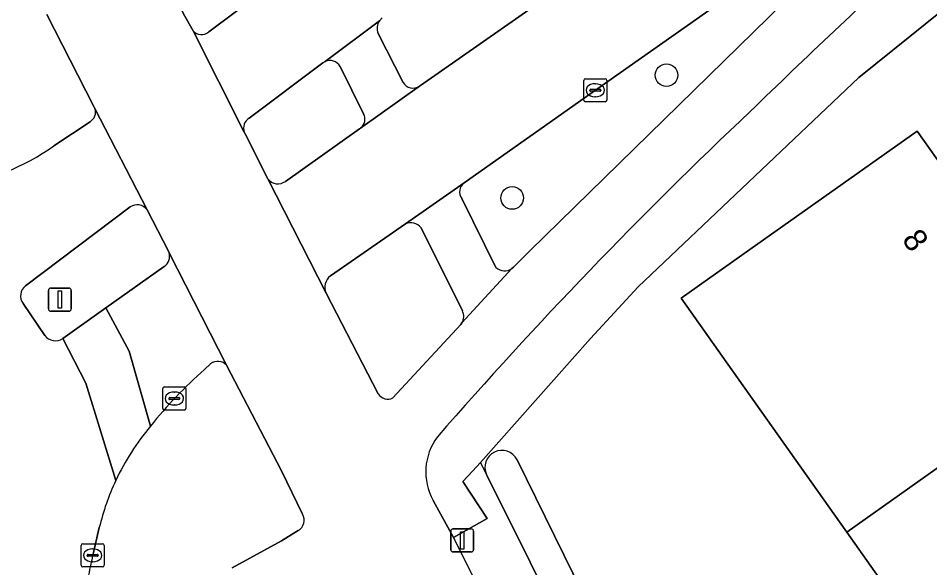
# Model space of a CAD drawing. Extents: x 158455 to 159797, y 387218 to 388672.
# Drawn here: x 159177.48 to 159216.88, y 387740.08 to 387763.85 of the extents above; entities that cross this region are included whole.
import ezdxf

# ---------------------------------------------------------------- set-up
doc = ezdxf.new("R2010")
doc.units = 0
for name, color, linetype in [('IMGEO_Berm_groen', 7, 'Continuous'), ('IMGEO_Boom', 7, 'Continuous'), ('IMGEO_Erf', 7, 'Continuous'), ('IMGEO_Fietspad_open', 7, 'Continuous'), ('IMGEO_Kolk', 7, 'Continuous'), ('IMGEO_Lichtmast', 7, 'Continuous'), ('IMGEO_Pand', 7, 'Continuous'), ('IMGEO_Pand_nummerreeks', 7, 'Continuous'), ('IMGEO_Rijbaan_lokaal_gesloten', 7, 'Continuous'), ('IMGEO_Verkeerseiland_groen', 7, 'Continuous'), ('IMGEO_Voetpad_open', 7, 'Continuous'), ('IMGEO_Waterloop', 7, 'Continuous')]:
    doc.layers.add(name, color=color, linetype=linetype)

msp = doc.modelspace()

# ---------------------------------------------------------------- linework, layer by layer
at = {"layer": 'IMGEO_Berm_groen'}
for points in [[(159194.829, 387760.914), (159194.871, 387760.944), (159201.836, 387765.824)], [(159180.793, 387759.947), (159180.737, 387760.058), (159178.711, 387764.013)], [(159193.037, 387763.192), (159194.114, 387761.073)], [(159179.013, 387758.326), (159180.582, 387759.371)], [(159197.72, 387744.115), (159197.458, 387744.641), (159197.12, 387744.26), (159196.694, 387743.819), (159197.747, 387742.215), (159196.287, 387741.387), (159199.422, 387735.133), (159203.135, 387727.729), (159203.744, 387726.53), (159209.072, 387716.044), (159215.088, 387713.348), (159215.858, 387713.235), (159217.158, 387713.181), (159235.947, 387712.585), (159235.969, 387713.133), (159236.15, 387717.664), (159235.73, 387717.691), (159234.304, 387717.222)], [(159210.934, 387717.576), (159197.72, 387744.115)]]:
    msp.add_lwpolyline(points, dxfattribs=at)
for centre, radius, start, end in [((159193.535, 387763.415), 0.546, 143.5726, 204.115), ((159193.553, 387763.402), 0.568, 127.9426, 143.6271), ((159194.549, 387761.342), 0.512, 211.7615, 303.1639), ((159180.336, 387759.788), 0.484, 300.5909, 19.1716), ((159173.217, 387766.521), 10.038, 278.3038, 305.2672)]:
    msp.add_arc(centre, radius, start, end, dxfattribs=at)
at = {"layer": 'IMGEO_Boom'}
for centre in [(159205.5, 387761.384), (159198.83, 387756.077)]:
    msp.add_circle(centre, 0.489, dxfattribs=at)
at = {"layer": 'IMGEO_Erf'}
for points in [[(159236.179, 387728.753), (159235.227, 387730.066), (159229.26, 387738.298), (159232.294, 387740.557), (159225.442, 387750), (159223.511, 387752.661), (159224.515, 387753.447), (159223.591, 387757.291), (159218.155, 387764.796), (159213.819, 387761.288), (159204.282, 387752.237), (159202.211, 387750), (159197.458, 387744.641), (159197.72, 387744.115)], [(159217.899, 387735.111), (159213.29, 387741.626), (159208.321, 387748.651), (159206.13, 387751.748), (159209.096, 387753.846), (159216.34, 387758.971), (159220.621, 387752.92)], [(159199.04, 387744.753), (159211.918, 387718.548)]]:
    msp.add_lwpolyline(points, dxfattribs=at)
msp.add_arc((159198.382, 387744.429), 0.733, 26.2174, 205.3746, dxfattribs=at)
at = {"layer": 'IMGEO_Fietspad_open'}
for points in [[(159216.449, 387766.728), (159214.491, 387768.328), (159213.131, 387767.053), (159199.59, 387753.792), (159198.894, 387753.089), (159198.822, 387753.027), (159196.659, 387750.67), (159196.609, 387750.601), (159193.667, 387747.428)], [(159193.037, 387747.602), (159190.786, 387751.953), (159188.274, 387756.909), (159187.3, 387758.822), (159187.247, 387758.928), (159185.04, 387763.304), (159184.617, 387764.04), (159183.73, 387765.91)], [(159178.711, 387764.013), (159180.737, 387760.058), (159180.793, 387759.947), (159183.05, 387755.565), (159183.974, 387753.779), (159184.002, 387753.705), (159186.488, 387748.842), (159188.852, 387744.277), (159189.771, 387742.404)], [(159188.426, 387738.045), (159190.99, 387739.621), (159191.191, 387739.744), (159191.822, 387738.536), (159194.686, 387732.684), (159199.422, 387735.133), (159196.287, 387741.387), (159195.41, 387742.999)], [(159189.581, 387741.691), (159188.857, 387741.243), (159186.728, 387740.084)]]:
    msp.add_lwpolyline(points, dxfattribs=at)
for centre, radius, start, end in [((159441.931, 387520.228), 334.072, 132.45033, 134.17723), ((159347.221, 387613.579), 201.141, 133.35949, 138.92324), ((159193.45, 387747.87), 0.492, 212.9441, 296.1766), ((159197.638, 387744.227), 2.544, 143.4188, 208.8672), ((159189.302, 387742.147), 0.534, 301.4159, 28.7413)]:
    msp.add_arc(centre, radius, start, end, dxfattribs=at)
at = {"layer": 'IMGEO_Kolk'}
for p, q in [((159201.924, 387760.309), (159201.924, 387761.161)), ((159201.999, 387761.235), (159202.851, 387761.235)), ((159202.925, 387761.161), (159202.925, 387760.309)), ((159202.183, 387760.729), (159202.183, 387760.741)), ((159202.226, 387760.778), (159202.624, 387760.778)), ((159202.412, 387761.015), (159202.437, 387761.015)), ((159202.667, 387760.741), (159202.667, 387760.729)), ((159202.621, 387760.692), (159202.223, 387760.692)), ((159202.435, 387760.455), (159202.41, 387760.455)), ((159202.851, 387760.235), (159201.999, 387760.235)), ((159183.727, 387746.978), (159183.727, 387747.83)), ((159183.802, 387747.904), (159184.654, 387747.904)), ((159184.728, 387747.83), (159184.728, 387746.978)), ((159183.986, 387747.398), (159183.986, 387747.41)), ((159184.424, 387747.361), (159184.026, 387747.361)), ((159184.029, 387747.447), (159184.427, 387747.447)), ((159184.215, 387747.684), (159184.24, 387747.684)), ((159184.47, 387747.41), (159184.47, 387747.398)), ((159184.238, 387747.124), (159184.213, 387747.124)), ((159184.654, 387746.904), (159183.802, 387746.904)), ((159180.196, 387740.196), (159180.196, 387741.048)), ((159180.271, 387741.122), (159181.123, 387741.122)), ((159181.197, 387741.048), (159181.197, 387740.196)), ((159180.455, 387740.616), (159180.455, 387740.628)), ((159180.498, 387740.665), (159180.896, 387740.665)), ((159180.684, 387740.902), (159180.709, 387740.902)), ((159180.939, 387740.628), (159180.939, 387740.616)), ((159180.893, 387740.579), (159180.495, 387740.579)), ((159180.707, 387740.342), (159180.682, 387740.342)), ((159181.123, 387740.122), (159180.271, 387740.122))]:
    msp.add_line(p, q, dxfattribs=at)
for points in [[(159201.924, 387760.309), (159201.924, 387761.161)], [(159201.999, 387761.235), (159202.851, 387761.235)], [(159202.925, 387761.161), (159202.925, 387760.309)], [(159202.851, 387760.235), (159201.999, 387760.235)], [(159183.727, 387746.978), (159183.727, 387747.83)], [(159183.802, 387747.904), (159184.654, 387747.904)], [(159184.728, 387747.83), (159184.728, 387746.978)], [(159184.654, 387746.904), (159183.802, 387746.904)], [(159180.196, 387740.196), (159180.196, 387741.048)], [(159180.271, 387741.122), (159181.123, 387741.122)], [(159181.197, 387741.048), (159181.197, 387740.196)], [(159181.123, 387740.122), (159180.271, 387740.122)]]:
    msp.add_lwpolyline(points, dxfattribs=at)
for centre, radius, start, end in [((159202.001, 387761.159), 0.0765, 91.552, 178.448), ((159202.001, 387761.159), 0.0765, 91.552, 178.448), ((159202.849, 387761.159), 0.0765, 1.552, 88.448), ((159202.849, 387761.159), 0.0765, 1.552, 88.448), ((159202.223, 387760.738), 0.0403, 85.8775, 175.7526), ((159202.22, 387760.728), 0.0366, 178.938, 274.7102), ((159202.624, 387760.735), 0.043, 264.8664, 352.4533), ((159202.628, 387760.74), 0.0386, 1.7309, 96.639), ((159202.001, 387760.311), 0.0765, 181.552, 268.448), ((159202.001, 387760.311), 0.0765, 181.552, 268.448), ((159202.849, 387760.311), 0.0765, 271.552, 358.448), ((159202.849, 387760.311), 0.0765, 271.552, 358.448), ((159183.804, 387747.828), 0.0765, 91.552, 178.448), ((159183.804, 387747.828), 0.0765, 91.552, 178.448), ((159184.652, 387747.828), 0.0765, 1.552, 88.448), ((159184.652, 387747.828), 0.0765, 1.552, 88.448), ((159184.026, 387747.407), 0.0403, 85.8775, 175.7526), ((159184.023, 387747.397), 0.0366, 178.938, 274.7102), ((159184.427, 387747.404), 0.043, 264.8664, 352.4533), ((159184.431, 387747.409), 0.0386, 1.7309, 96.639), ((159183.804, 387746.98), 0.0765, 181.552, 268.448), ((159183.804, 387746.98), 0.0765, 181.552, 268.448), ((159184.652, 387746.98), 0.0765, 271.552, 358.448), ((159184.652, 387746.98), 0.0765, 271.552, 358.448), ((159180.273, 387741.046), 0.0765, 91.552, 178.448), ((159180.273, 387741.046), 0.0765, 91.552, 178.448), ((159181.121, 387741.046), 0.0765, 1.552, 88.448), ((159181.121, 387741.046), 0.0765, 1.552, 88.448), ((159180.495, 387740.625), 0.0403, 85.8775, 175.7526), ((159180.9, 387740.627), 0.0386, 1.7309, 96.639), ((159180.492, 387740.615), 0.0366, 178.938, 274.7102), ((159180.896, 387740.622), 0.043, 264.8664, 352.4533), ((159180.273, 387740.198), 0.0765, 181.552, 268.448), ((159180.273, 387740.198), 0.0765, 181.552, 268.448), ((159181.121, 387740.198), 0.0765, 271.552, 358.448), ((159181.121, 387740.198), 0.0765, 271.552, 358.448)]:
    msp.add_arc(centre, radius, start, end, dxfattribs=at)
for centre, major_axis, ratio, start_param, end_param in [((159202.411, 387760.735), (-0.387, 0.002), 0.722429, 4.712389, 7.853982), ((159202.436, 387760.735), (-0.39, 0.002), 0.717154, 1.570796, 4.712389), ((159184.214, 387747.404), (-0.387, 0.002), 0.722429, 4.712389, 7.853982), ((159184.239, 387747.404), (-0.39, 0.002), 0.717154, 1.570796, 4.712389), ((159180.683, 387740.622), (-0.387, 0.002), 0.722429, 4.712389, 7.853982), ((159180.708, 387740.622), (-0.39, 0.002), 0.717154, 1.570796, 4.712389)]:
    msp.add_ellipse(centre, major_axis=major_axis, ratio=ratio, start_param=start_param, end_param=end_param, dxfattribs=at)
at = {"layer": 'IMGEO_Lichtmast'}
for p, q in [((159178.784, 387751.28), (159178.784, 387752.08)), ((159178.784, 387752.08), (159178.784, 387751.28)), ((159178.884, 387752.18), (159179.674, 387752.18)), ((159179.674, 387752.18), (159178.884, 387752.18)), ((159179.774, 387752.08), (159179.774, 387751.28)), ((159179.774, 387751.28), (159179.774, 387752.08)), ((159179.674, 387751.18), (159178.884, 387751.18)), ((159178.884, 387751.18), (159179.674, 387751.18)), ((159196.172, 387740.867), (159196.172, 387741.667)), ((159196.172, 387741.667), (159196.172, 387740.867)), ((159196.272, 387741.767), (159197.062, 387741.767)), ((159197.062, 387741.767), (159196.272, 387741.767)), ((159197.162, 387741.667), (159197.162, 387740.867)), ((159197.162, 387740.867), (159197.162, 387741.667)), ((159197.062, 387740.767), (159196.272, 387740.767)), ((159196.272, 387740.767), (159197.062, 387740.767))]:
    msp.add_line(p, q, dxfattribs=at)
for points in [[(159179.204, 387752.055), (159179.354, 387752.055), (159179.354, 387751.305), (159179.204, 387751.305), (159179.204, 387752.055)], [(159196.592, 387741.642), (159196.742, 387741.642), (159196.742, 387740.892), (159196.592, 387740.892), (159196.592, 387741.642)]]:
    msp.add_lwpolyline(points, dxfattribs=at)
for centre, start, end in [((159178.884, 387752.08), 90, 180), ((159178.884, 387752.08), 90, 180), ((159179.674, 387752.08), 0, 90), ((159179.674, 387752.08), 360, 90), ((159178.884, 387751.28), 180, 270), ((159178.884, 387751.28), 180, 270), ((159179.674, 387751.28), 270, 0), ((159179.674, 387751.28), 270, 0), ((159196.272, 387741.667), 90, 180), ((159196.272, 387741.667), 90, 180), ((159197.062, 387741.667), 0, 90), ((159197.062, 387741.667), 360, 90), ((159196.272, 387740.867), 180, 270), ((159196.272, 387740.867), 180, 270), ((159197.062, 387740.867), 270, 0), ((159197.062, 387740.867), 270, 0)]:
    msp.add_arc(centre, 0.1, start, end, dxfattribs=at)
at = {"layer": 'IMGEO_Pand'}
for points in [[(159217.973, 387751.046), (159220.621, 387752.92), (159216.34, 387758.971), (159209.096, 387753.846), (159206.13, 387751.748), (159208.321, 387748.651), (159213.29, 387741.626), (159219.44, 387745.978), (159220.851, 387746.977), (159218.713, 387750)], [(159219.527, 387745.855), (159219.44, 387745.978), (159213.29, 387741.626), (159217.899, 387735.111), (159219.374, 387736.154), (159221.405, 387733.283), (159221.54, 387733.092), (159224.79, 387735.39), (159228.92, 387738.31), (159224.896, 387743.997), (159222.194, 387742.085)]]:
    msp.add_lwpolyline(points, close=True, dxfattribs=at)
at = {"layer": 'IMGEO_Rijbaan_lokaal_gesloten'}
for points in [[(159206.931, 387769.424), (159204.04, 387767.381), (159201.836, 387765.824), (159194.871, 387760.944), (159194.829, 387760.914), (159192.279, 387759.096), (159192.256, 387759.079), (159192.233, 387759.064), (159189.028, 387756.796)], [(159190.974, 387752.703), (159194.223, 387754.955), (159196.748, 387756.729), (159202.425, 387760.735), (159214.068, 387768.944)], [(159194.975, 387765.188), (159192.602, 387768.409), (159191.435, 387767.536), (159189.023, 387765.739), (159185.711, 387763.256)], [(159187.459, 387759.529), (159190.644, 387761.924), (159190.744, 387761.979), (159193.096, 387763.739)], [(159185.04, 387763.304), (159187.247, 387758.928)], [(159183.05, 387755.565), (159180.793, 387759.947)], [(159180.582, 387759.371), (159179.013, 387758.326)], [(159188.274, 387756.909), (159190.786, 387751.953)], [(159177.796, 387752.278), (159182.318, 387755.692)], [(159186.488, 387748.842), (159184.002, 387753.705)], [(159183.792, 387753.111), (159181.266, 387751.323), (159182.275, 387749.457), (159183.195, 387746.204)], [(159178.63, 387750.132), (159177.689, 387751.508)], [(159182.275, 387749.457), (159181.266, 387751.323), (159179.4, 387750.002), (159180.407, 387748.068), (159181.694, 387743.855)], [(159181.694, 387743.855), (159180.407, 387748.068), (159179.4, 387750.002)], [(159183.195, 387746.204), (159182.275, 387749.457)], [(159185.533, 387748.652), (159185.796, 387748.908)], [(159180.697, 387740.622), (159180.984, 387741.83)]]:
    msp.add_lwpolyline(points, dxfattribs=at)
for centre, radius, start, end in [((159193.553, 387763.402), 0.568, 127.9426, 143.6271), ((159185.399, 387763.609), 0.471, 220.331, 311.4856), ((159180.336, 387759.788), 0.484, 300.5909, 19.1716), ((159187.718, 387759.1), 0.501, 121.0889, 200.0509), ((159173.217, 387766.521), 10.038, 278.3038, 305.2672), ((159188.705, 387757.216), 0.53, 215.4314, 307.5219), ((159182.617, 387755.239), 0.542, 36.9041, 123.4105), ((159183.486, 387753.553), 0.538, 304.676, 16.3834), ((159191.359, 387752.208), 0.627, 127.8536, 204.002), ((159178.139, 387751.838), 0.558, 127.9599, 216.2177), ((159179.082, 387750.463), 0.56, 216.2482, 304.5859), ((159186.105, 387748.484), 0.524, 43.0251, 126.0786), ((159197.563, 387734.823), 18.329, 131.0183, 141.615), ((159191.477, 387739.258), 10.809, 140.0131, 154.8301), ((159191.214, 387739.38), 10.519, 154.8242, 166.5327), ((159196.205, 387737.027), 15.92, 166.9478, 170.5665)]:
    msp.add_arc(centre, radius, start, end, dxfattribs=at)
at = {"layer": 'IMGEO_Verkeerseiland_groen'}
for points in [[(159214.068, 387768.944), (159202.425, 387760.735), (159196.748, 387756.729)], [(159198.822, 387753.027), (159198.894, 387753.089), (159199.59, 387753.792), (159213.131, 387767.053)], [(159183.73, 387765.91), (159184.617, 387764.04), (159185.04, 387763.304)], [(159185.711, 387763.256), (159189.023, 387765.739)], [(159190.744, 387761.979), (159190.644, 387761.924), (159187.459, 387759.529)], [(159192.404, 387759.722), (159191.396, 387761.766)], [(159187.247, 387758.928), (159187.3, 387758.822), (159188.274, 387756.909)], [(159189.028, 387756.796), (159192.233, 387759.064), (159192.256, 387759.079), (159192.279, 387759.096)], [(159196.648, 387756.059), (159198.13, 387753.067)], [(159182.318, 387755.692), (159177.796, 387752.278)], [(159184.002, 387753.705), (159183.974, 387753.779), (159183.05, 387755.565)], [(159194.223, 387754.955), (159190.974, 387752.703)], [(159196.676, 387751.195), (159194.891, 387754.786)], [(159179.4, 387750.002), (159181.266, 387751.323), (159183.792, 387753.111)], [(159190.786, 387751.953), (159193.037, 387747.602)], [(159177.689, 387751.508), (159178.63, 387750.132)], [(159193.667, 387747.428), (159196.609, 387750.601), (159196.659, 387750.67)], [(159185.796, 387748.908), (159185.533, 387748.652)], [(159189.771, 387742.404), (159188.852, 387744.277), (159186.488, 387748.842)], [(159180.984, 387741.83), (159180.697, 387740.622)], [(159186.728, 387740.084), (159188.857, 387741.243), (159189.581, 387741.691)]]:
    msp.add_lwpolyline(points, dxfattribs=at)
for centre, radius, start, end in [((159185.399, 387763.609), 0.471, 220.331, 311.4856), ((159190.947, 387761.496), 0.524, 31.0493, 112.7676), ((159191.976, 387759.482), 0.491, 308.1676, 29.2477), ((159187.718, 387759.1), 0.501, 121.0889, 200.0509), ((159188.705, 387757.216), 0.53, 215.4314, 307.5219), ((159197.045, 387756.342), 0.488, 127.5359, 215.4862), ((159182.617, 387755.239), 0.542, 36.9041, 123.4105), ((159194.443, 387754.421), 0.577, 39.1744, 112.4304), ((159183.486, 387753.553), 0.538, 304.676, 16.3834), ((159198.501, 387753.474), 0.55, 227.6501, 305.7335), ((159191.359, 387752.208), 0.627, 127.8536, 204.002), ((159178.139, 387751.838), 0.558, 127.9599, 216.2177), ((159196.204, 387750.948), 0.533, 328.628, 27.6627), ((159179.082, 387750.463), 0.56, 216.2482, 304.5859), ((159186.105, 387748.484), 0.524, 43.0251, 126.0786), ((159197.563, 387734.823), 18.329, 131.0183, 141.615), ((159193.45, 387747.87), 0.492, 212.9441, 296.1766), ((159191.477, 387739.258), 10.809, 140.0131, 154.8301), ((159191.214, 387739.38), 10.519, 154.8242, 166.5327), ((159189.302, 387742.147), 0.534, 301.4159, 28.7413), ((159196.205, 387737.027), 15.92, 166.9478, 170.5665)]:
    msp.add_arc(centre, radius, start, end, dxfattribs=at)
at = {"layer": 'IMGEO_Voetpad_open'}
for points in [[(159195.41, 387742.999), (159196.287, 387741.387), (159197.747, 387742.215), (159196.694, 387743.819), (159197.12, 387744.26), (159197.458, 387744.641), (159202.211, 387750), (159204.282, 387752.237), (159213.819, 387761.288), (159218.155, 387764.796), (159219.866, 387766.077), (159303.107, 387825.734), (159307.132, 387828.619), (159309.204, 387832.674)], [(159193.096, 387763.739), (159190.744, 387761.979)], [(159194.114, 387761.073), (159193.037, 387763.192)], [(159191.396, 387761.766), (159192.404, 387759.722)], [(159192.279, 387759.096), (159194.829, 387760.914)], [(159196.748, 387756.729), (159194.223, 387754.955)], [(159198.13, 387753.067), (159196.648, 387756.059)], [(159194.891, 387754.786), (159196.676, 387751.195)], [(159196.659, 387750.67), (159198.822, 387753.027)]]:
    msp.add_lwpolyline(points, dxfattribs=at)
for centre, radius, start, end in [((159441.931, 387520.228), 334.072, 132.45033, 134.17723), ((159193.535, 387763.415), 0.546, 143.5726, 204.115), ((159190.947, 387761.496), 0.524, 31.0493, 112.7676), ((159194.549, 387761.342), 0.512, 211.7615, 303.1639), ((159191.976, 387759.482), 0.491, 308.1676, 29.2477), ((159347.221, 387613.579), 201.141, 133.35949, 138.92324), ((159197.045, 387756.342), 0.488, 127.5359, 215.4862), ((159194.443, 387754.421), 0.577, 39.1744, 112.4304), ((159198.501, 387753.474), 0.55, 227.6501, 305.7335), ((159196.204, 387750.948), 0.533, 328.628, 27.6627), ((159197.638, 387744.227), 2.544, 143.4188, 208.8672)]:
    msp.add_arc(centre, radius, start, end, dxfattribs=at)
at = {"layer": 'IMGEO_Waterloop'}
for points in [[(159211.918, 387718.548), (159199.04, 387744.753)], [(159197.72, 387744.115), (159210.934, 387717.576)]]:
    msp.add_lwpolyline(points, dxfattribs=at)
msp.add_arc((159198.382, 387744.429), 0.733, 26.2174, 205.3746, dxfattribs=at)

# ---------------------------------------------------------------- texts
at = {"layer": 'IMGEO_Pand_nummerreeks'}
msp.add_text('8', height=1, rotation=305.2768, dxfattribs=at).set_placement((159215.646, 387754.273))

doc.saveas('drawing.dxf')
